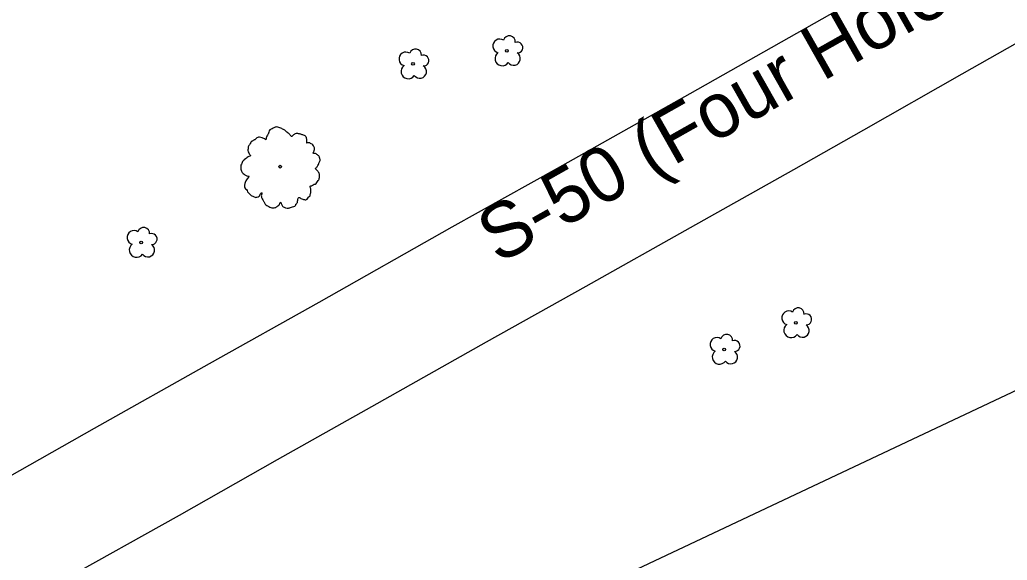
# Model space of a CAD drawing. Extents: x 2076109 to 2080761, y 592812 to 596750.
# Drawn here: x 2076956.7 to 2077136.1, y 595575.9 to 595674.2 of the extents above; entities that cross this region are included whole.
import ezdxf

# ---------------------------------------------------------------- set-up
doc = ezdxf.new("R2010")
doc.units = 0
for name, color, linetype in [('Default', 7, 'Continuous'), ('RD_EX_Road', 7, 'Continuous'), ('RD_EX_UT', 7, 'Continuous'), ('RD_EX_VEG', 7, 'Continuous'), ('RD_PD_ALT5_TX', 7, 'Continuous')]:
    doc.layers.add(name, color=color, linetype=linetype)

msp = doc.modelspace()

# ---------------------------------------------------------------- linework, layer by layer
at = {"layer": 'Default'}
msp.add_arc((2035586.7, 547847.96), 63546.51, 48.5011873, 49.2923126, dxfattribs=at)
msp.add_arc((2035586.7, 547847.96), 63546.51, 48.5011873, 49.2923126, dxfattribs=at)
at = {"layer": 'RD_EX_Road'}
for points in [[(2076946.71, 595586.58), (2076970.23, 595599.97), (2076991.14, 595611.71), (2077011.07, 595622.89), (2077035.24, 595636.56), (2077054.39, 595647.26), (2077078.47, 595660.82), (2077103.87, 595675.19), (2077125.16, 595687.16), (2077145.98, 595698.79), (2077169.84, 595712.59), (2077173.44, 595715.27), (2077179.13, 595719.49), (2077185.08, 595723.44)], [(2076946.71, 595586.58), (2076970.23, 595599.97), (2076991.14, 595611.71), (2077011.07, 595622.89), (2077035.24, 595636.56), (2077054.39, 595647.26), (2077078.47, 595660.82), (2077103.87, 595675.19), (2077125.16, 595687.16), (2077145.98, 595698.79), (2077169.84, 595712.59), (2077173.44, 595715.27), (2077179.13, 595719.49), (2077185.08, 595723.44)], [(2076946.45, 595562.46), (2076964.21, 595572.12), (2076985.67, 595584.13), (2077003.53, 595594.22), (2077020.62, 595603.86), (2077041.5, 595615.67), (2077059.57, 595625.8), (2077078.55, 595636.46), (2077097.33, 595647.01), (2077110.03, 595654.24), (2077127.93, 595664.39), (2077149.02, 595676.34), (2077165.44, 595685.72), (2077186.78, 595697.64), (2077191.37, 595700.15), (2077199.53, 595704.6), (2077201.82, 595704.54), (2077204.49, 595706.23)], [(2076946.45, 595562.46), (2076964.21, 595572.12), (2076985.67, 595584.13), (2077003.53, 595594.22), (2077020.62, 595603.86), (2077041.5, 595615.67), (2077059.57, 595625.8), (2077078.55, 595636.46), (2077097.33, 595647.01), (2077110.03, 595654.24), (2077127.93, 595664.39), (2077149.02, 595676.34), (2077165.44, 595685.72), (2077186.78, 595697.64), (2077191.37, 595700.15), (2077199.53, 595704.6), (2077201.82, 595704.54), (2077204.49, 595706.23)]]:
    msp.add_lwpolyline(points, dxfattribs=at)
at = {"layer": 'RD_EX_UT'}
msp.add_line((2076957.46, 595521.79), (2077194.62, 595633.66), dxfattribs=at)
msp.add_line((2076957.46, 595521.79), (2077194.62, 595633.66), dxfattribs=at)
at = {"layer": 'RD_EX_VEG'}
for centre, radius in [((2077045.19, 595668.57), 0.25), ((2077045.19, 595668.57), 0.25), ((2077028.13, 595666.2), 0.25), ((2077028.13, 595666.2), 0.25), ((2077004, 595647.51), 0.25), ((2077004, 595647.51), 0.25), ((2077003.98, 595647.5), 0.0001), ((2077003.98, 595647.5), 0.0001), ((2076978.73, 595633.73), 0.25), ((2076978.73, 595633.73), 0.25), ((2077097.68, 595619.11), 0.25), ((2077097.68, 595619.11), 0.25), ((2077084.67, 595614.27), 0.25), ((2077084.67, 595614.27), 0.25)]:
    msp.add_circle(centre, radius, dxfattribs=at)
for centre, radius, start, end in [((2077045.64, 595670.22), 1.08, 354.6037, 164.3834), ((2077045.64, 595670.22), 1.08, 354.6037, 164.3834), ((2077043.9, 595669.46), 1.26, 56.0792, 254.3614), ((2077043.9, 595669.46), 1.26, 56.0792, 254.3614), ((2077047.09, 595669.19), 0.995, 268.39, 111.6741), ((2077047.09, 595669.19), 0.995, 268.39, 111.6741), ((2077026.83, 595667.1), 1.26, 56.0792, 254.3614), ((2077026.83, 595667.1), 1.26, 56.0792, 254.3614), ((2077028.58, 595667.85), 1.08, 354.6037, 164.3834), ((2077028.58, 595667.85), 1.08, 354.6037, 164.3834), ((2077030.02, 595666.82), 0.995, 268.39, 111.6741), ((2077030.02, 595666.82), 0.995, 268.39, 111.6741), ((2077044.35, 595667.19), 1.32, 126.51, 325.3863), ((2077044.35, 595667.19), 1.32, 126.51, 325.3863), ((2077046.41, 595667.17), 1.22, 216.1941, 57.732), ((2077046.41, 595667.17), 1.22, 216.1941, 57.732), ((2077027.28, 595664.83), 1.32, 126.51, 325.3863), ((2077027.28, 595664.83), 1.32, 126.51, 325.3863), ((2077029.35, 595664.8), 1.22, 216.1941, 57.732), ((2077029.35, 595664.8), 1.22, 216.1941, 57.732), ((2076977.44, 595634.62), 1.26, 56.0792, 254.3614), ((2076977.44, 595634.62), 1.26, 56.0792, 254.3614), ((2076979.19, 595635.37), 1.08, 354.6037, 164.3834), ((2076979.19, 595635.37), 1.08, 354.6037, 164.3834), ((2076980.63, 595634.34), 0.995, 268.39, 111.6741), ((2076980.63, 595634.34), 0.995, 268.39, 111.6741), ((2076977.89, 595632.35), 1.32, 126.51, 325.3863), ((2076977.89, 595632.35), 1.32, 126.51, 325.3863), ((2076979.95, 595632.32), 1.22, 216.1941, 57.732), ((2076979.95, 595632.32), 1.22, 216.1941, 57.732), ((2077096.39, 595620), 1.26, 56.0792, 254.3614), ((2077096.39, 595620), 1.26, 56.0792, 254.3614), ((2077098.13, 595620.75), 1.08, 354.6037, 164.3834), ((2077098.13, 595620.75), 1.08, 354.6037, 164.3834), ((2077099.58, 595619.73), 0.995, 268.39, 111.6741), ((2077099.58, 595619.73), 0.995, 268.39, 111.6741), ((2077096.83, 595617.73), 1.32, 126.51, 325.3863), ((2077096.83, 595617.73), 1.32, 126.51, 325.3863), ((2077098.9, 595617.7), 1.22, 216.1941, 57.732), ((2077098.9, 595617.7), 1.22, 216.1941, 57.732), ((2077083.37, 595615.17), 1.26, 56.0792, 254.3614), ((2077083.37, 595615.17), 1.26, 56.0792, 254.3614), ((2077085.12, 595615.92), 1.08, 354.6037, 164.3834), ((2077085.12, 595615.92), 1.08, 354.6037, 164.3834), ((2077086.56, 595614.89), 0.995, 268.39, 111.6741), ((2077086.56, 595614.89), 0.995, 268.39, 111.6741), ((2077083.82, 595612.9), 1.32, 126.51, 325.3863), ((2077083.82, 595612.9), 1.32, 126.51, 325.3863), ((2077085.89, 595612.87), 1.22, 216.1941, 57.732), ((2077085.89, 595612.87), 1.22, 216.1941, 57.732)]:
    msp.add_arc(centre, radius, start, end, dxfattribs=at)
for points in [[(2077008.74, 595652.88), (2077008.53, 595653.1), (2077008.22, 595653.23), (2077007.96, 595653.32), (2077007.74, 595653.4), (2077007.51, 595653.47), (2077007.17, 595653.54), (2077006.87, 595653.53), (2077006.61, 595653.42), (2077006.42, 595653.28), (2077006.21, 595653.1), (2077006.1, 595652.97), (2077005.98, 595653.03), (2077005.89, 595653.15), (2077005.74, 595653.37), (2077005.55, 595653.53), (2077005.36, 595653.69), (2077005.08, 595653.9), (2077004.81, 595654.13), (2077004.57, 595654.26), (2077004.29, 595654.44), (2077003.93, 595654.59), (2077003.58, 595654.72), (2077003.19, 595654.72), (2077002.69, 595654.52), (2077002.37, 595654.33), (2077002.09, 595654.24), (2077001.91, 595653.8), (2077001.82, 595653.42), (2077001.71, 595653.25), (2077001.49, 595652.88), (2077001.42, 595652.65), (2077001.39, 595652.41), (2077001.32, 595652.44), (2077001, 595652.65), (2077000.7, 595652.76), (2077000.24, 595652.87), (2076999.92, 595652.84), (2076999.63, 595652.66), (2076999.39, 595652.41), (2076999.18, 595652.32), (2076998.95, 595652.16), (2076998.88, 595652.12), (2076998.63, 595651.9), (2076998.41, 595651.5), (2076998.21, 595651.21), (2076998.16, 595650.96), (2076998.16, 595650.73), (2076998.13, 595650.43), (2076998.29, 595650), (2076998.47, 595649.71), (2076998.61, 595649.56), (2076998.15, 595649.3), (2076997.88, 595649.06), (2076997.53, 595648.84), (2076997.48, 595648.78), (2076997.14, 595648.45), (2076997.04, 595648.11), (2076996.85, 595647.77), (2076996.84, 595647.49), (2076996.86, 595647.08), (2076996.96, 595646.7), (2076997.26, 595646.28), (2076997.58, 595646.04), (2076998.13, 595645.8), (2076998.37, 595645.7), (2076998.24, 595645.58), (2076998.01, 595645.28), (2076997.74, 595644.95), (2076997.64, 595644.61), (2076997.54, 595644.34), (2076997.49, 595644.05), (2076997.59, 595643.67), (2076997.85, 595643.35), (2076998.08, 595642.96), (2076998.37, 595642.61), (2076998.74, 595642.27), (2076999.29, 595642), (2076999.58, 595641.91), (2076999.77, 595641.98), (2077000.16, 595642.14), (2077000.27, 595642.34), (2077000.68, 595642.78), (2077000.64, 595642.58), (2077000.55, 595642.2), (2077000.74, 595641.65), (2077000.93, 595641.26), (2077001.19, 595640.84), (2077001.37, 595640.59), (2077001.78, 595640.34), (2077002.12, 595640.15), (2077002.48, 595640), (2077002.89, 595640.02), (2077003.2, 595640.11), (2077003.42, 595640.29), (2077003.72, 595640.53), (2077003.87, 595640.63)], [(2077008.74, 595652.88), (2077008.53, 595653.1), (2077008.22, 595653.23), (2077007.96, 595653.32), (2077007.74, 595653.4), (2077007.51, 595653.47), (2077007.17, 595653.54), (2077006.87, 595653.53), (2077006.61, 595653.42), (2077006.42, 595653.28), (2077006.21, 595653.1), (2077006.1, 595652.97), (2077005.98, 595653.03), (2077005.89, 595653.15), (2077005.74, 595653.37), (2077005.55, 595653.53), (2077005.36, 595653.69), (2077005.08, 595653.9), (2077004.81, 595654.13), (2077004.57, 595654.26), (2077004.29, 595654.44), (2077003.93, 595654.59), (2077003.58, 595654.72), (2077003.19, 595654.72), (2077002.69, 595654.52), (2077002.37, 595654.33), (2077002.09, 595654.24), (2077001.91, 595653.8), (2077001.82, 595653.42), (2077001.71, 595653.25), (2077001.49, 595652.88), (2077001.42, 595652.65), (2077001.39, 595652.41), (2077001.32, 595652.44), (2077001, 595652.65), (2077000.7, 595652.76), (2077000.24, 595652.87), (2076999.92, 595652.84), (2076999.63, 595652.66), (2076999.39, 595652.41), (2076999.18, 595652.32), (2076998.95, 595652.16), (2076998.88, 595652.12), (2076998.63, 595651.9), (2076998.41, 595651.5), (2076998.21, 595651.21), (2076998.16, 595650.96), (2076998.16, 595650.73), (2076998.13, 595650.43), (2076998.29, 595650), (2076998.47, 595649.71), (2076998.61, 595649.56), (2076998.15, 595649.3), (2076997.88, 595649.06), (2076997.53, 595648.84), (2076997.48, 595648.78), (2076997.14, 595648.45), (2076997.04, 595648.11), (2076996.85, 595647.77), (2076996.84, 595647.49), (2076996.86, 595647.08), (2076996.96, 595646.7), (2076997.26, 595646.28), (2076997.58, 595646.04), (2076998.13, 595645.8), (2076998.37, 595645.7), (2076998.24, 595645.58), (2076998.01, 595645.28), (2076997.74, 595644.95), (2076997.64, 595644.61), (2076997.54, 595644.34), (2076997.49, 595644.05), (2076997.59, 595643.67), (2076997.85, 595643.35), (2076998.08, 595642.96), (2076998.37, 595642.61), (2076998.74, 595642.27), (2076999.29, 595642), (2076999.58, 595641.91), (2076999.77, 595641.98), (2077000.16, 595642.14), (2077000.27, 595642.34), (2077000.68, 595642.78), (2077000.64, 595642.58), (2077000.55, 595642.2), (2077000.74, 595641.65), (2077000.93, 595641.26), (2077001.19, 595640.84), (2077001.37, 595640.59), (2077001.78, 595640.34), (2077002.12, 595640.15), (2077002.48, 595640), (2077002.89, 595640.02), (2077003.2, 595640.11), (2077003.42, 595640.29), (2077003.72, 595640.53), (2077003.87, 595640.63)], [(2077003.87, 595640.63), (2077003.92, 595640.81), (2077004.05, 595641.03), (2077004.09, 595640.97), (2077004.19, 595640.81), (2077004.32, 595640.54), (2077004.44, 595640.34), (2077004.7, 595640.15), (2077004.98, 595640.04), (2077005.5, 595639.96), (2077006.02, 595640.15), (2077006.48, 595640.27), (2077006.75, 595640.47), (2077006.86, 595640.68), (2077007.16, 595641.07), (2077007.17, 595641.39), (2077007.22, 595641.52), (2077007.4, 595641.89), (2077007.49, 595641.88), (2077007.73, 595641.74), (2077008.1, 595641.59), (2077008.39, 595641.51), (2077008.67, 595641.5), (2077008.88, 595641.62), (2077009.12, 595641.94), (2077009.41, 595642.21), (2077009.45, 595642.37), (2077009.47, 595642.55), (2077009.55, 595642.75), (2077009.53, 595642.97), (2077009.55, 595643.14), (2077009.54, 595643.29), (2077009.54, 595643.48), (2077009.49, 595643.69), (2077009.41, 595643.82), (2077009.46, 595643.97), (2077009.71, 595644.03), (2077009.81, 595644.07), (2077009.98, 595644.23), (2077010.37, 595644.35), (2077010.67, 595644.62), (2077010.91, 595644.97), (2077011.05, 595645.22), (2077011.11, 595645.52), (2077011.12, 595645.84), (2077011.14, 595646.06), (2077011.09, 595646.27), (2077010.92, 595646.57), (2077010.76, 595646.77), (2077010.5, 595647), (2077010.38, 595647.17), (2077010.43, 595647.19), (2077010.52, 595647.3), (2077010.7, 595647.51), (2077010.94, 595647.9), (2077011.15, 595648.38), (2077011.16, 595648.4), (2077011.25, 595648.65), (2077011.21, 595648.95), (2077011.14, 595649.14), (2077011.07, 595649.37), (2077010.89, 595649.55), (2077010.66, 595649.74), (2077010.42, 595649.88), (2077010.21, 595649.93), (2077009.99, 595649.95), (2077010.03, 595650.12), (2077010.15, 595650.41), (2077010.21, 595650.56), (2077010.21, 595650.79), (2077010.17, 595651.08), (2077009.9, 595651.47), (2077009.38, 595651.82), (2077009.02, 595651.86), (2077008.79, 595651.82), (2077008.84, 595651.95), (2077008.81, 595652.23), (2077008.85, 595652.43), (2077008.8, 595652.64), (2077008.75, 595652.81), (2077008.71, 595652.92)], [(2077003.87, 595640.63), (2077003.92, 595640.81), (2077004.05, 595641.03), (2077004.09, 595640.97), (2077004.19, 595640.81), (2077004.32, 595640.54), (2077004.44, 595640.34), (2077004.7, 595640.15), (2077004.98, 595640.04), (2077005.5, 595639.96), (2077006.02, 595640.15), (2077006.48, 595640.27), (2077006.75, 595640.47), (2077006.86, 595640.68), (2077007.16, 595641.07), (2077007.17, 595641.39), (2077007.22, 595641.52), (2077007.4, 595641.89), (2077007.49, 595641.88), (2077007.73, 595641.74), (2077008.1, 595641.59), (2077008.39, 595641.51), (2077008.67, 595641.5), (2077008.88, 595641.62), (2077009.12, 595641.94), (2077009.41, 595642.21), (2077009.45, 595642.37), (2077009.47, 595642.55), (2077009.55, 595642.75), (2077009.53, 595642.97), (2077009.55, 595643.14), (2077009.54, 595643.29), (2077009.54, 595643.48), (2077009.49, 595643.69), (2077009.41, 595643.82), (2077009.46, 595643.97), (2077009.71, 595644.03), (2077009.81, 595644.07), (2077009.98, 595644.23), (2077010.37, 595644.35), (2077010.67, 595644.62), (2077010.91, 595644.97), (2077011.05, 595645.22), (2077011.11, 595645.52), (2077011.12, 595645.84), (2077011.14, 595646.06), (2077011.09, 595646.27), (2077010.92, 595646.57), (2077010.76, 595646.77), (2077010.5, 595647), (2077010.38, 595647.17), (2077010.43, 595647.19), (2077010.52, 595647.3), (2077010.7, 595647.51), (2077010.94, 595647.9), (2077011.15, 595648.38), (2077011.16, 595648.4), (2077011.25, 595648.65), (2077011.21, 595648.95), (2077011.14, 595649.14), (2077011.07, 595649.37), (2077010.89, 595649.55), (2077010.66, 595649.74), (2077010.42, 595649.88), (2077010.21, 595649.93), (2077009.99, 595649.95), (2077010.03, 595650.12), (2077010.15, 595650.41), (2077010.21, 595650.56), (2077010.21, 595650.79), (2077010.17, 595651.08), (2077009.9, 595651.47), (2077009.38, 595651.82), (2077009.02, 595651.86), (2077008.79, 595651.82), (2077008.84, 595651.95), (2077008.81, 595652.23), (2077008.85, 595652.43), (2077008.8, 595652.64), (2077008.75, 595652.81), (2077008.71, 595652.92)]]:
    msp.add_spline(points, degree=3, dxfattribs=at)

# ---------------------------------------------------------------- texts
at = {"layer": 'RD_PD_ALT5_TX'}
msp.add_text('S-50 (Four Holes Road)', height=10, rotation=29.4729, dxfattribs=at).set_placement((2077043.65, 595629.66))
msp.add_text('S-50 (Four Holes Road)', height=10, rotation=29.4729, dxfattribs=at).set_placement((2077043.65, 595629.66))

doc.saveas('drawing.dxf')
